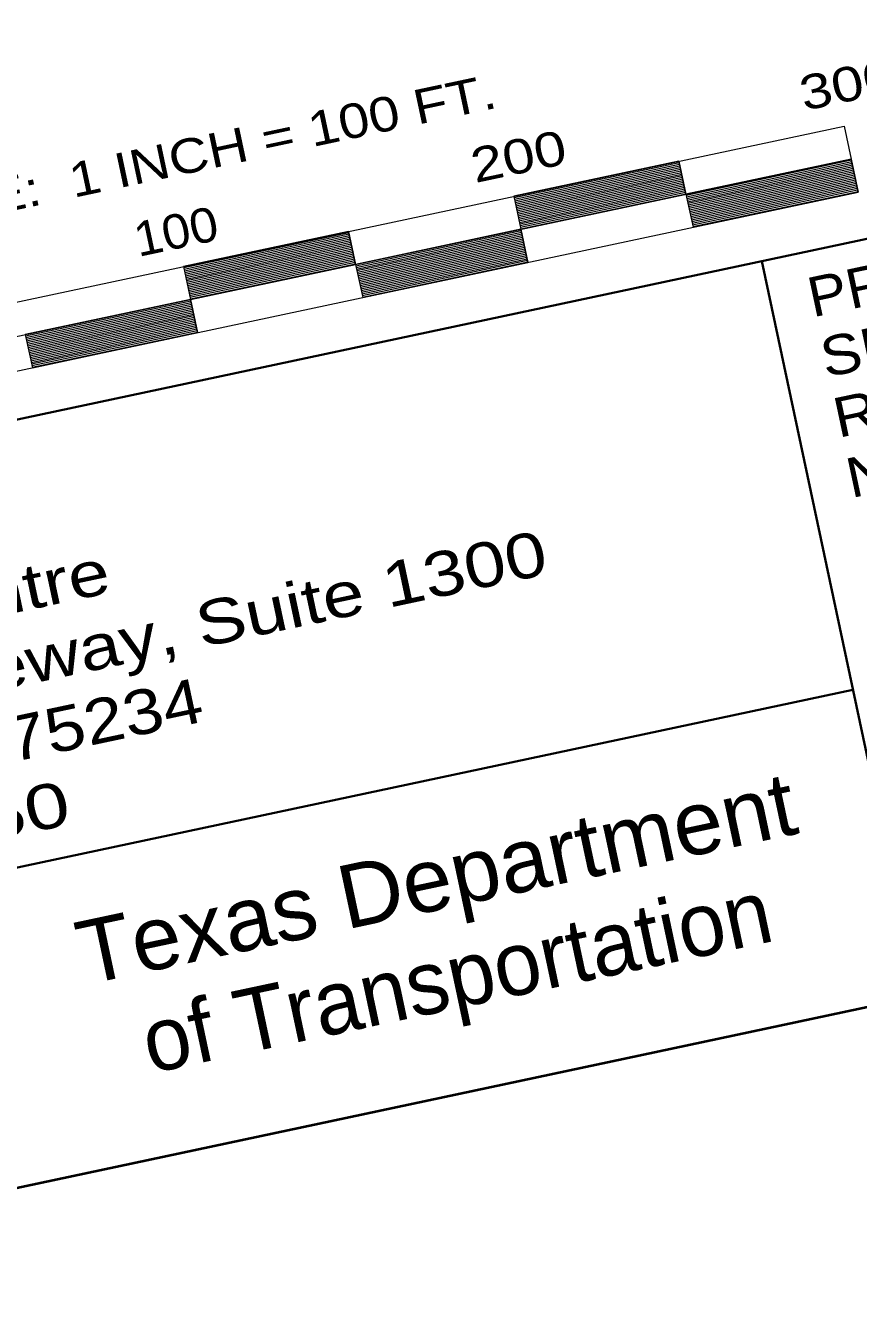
# Model space of a CAD drawing. Extents: x 2357218 to 2371708, y 6973728 to 6980157.
# Drawn here: x 2358239.3 to 2358486, y 6973919.3 to 6974296.3 of the extents above; entities that cross this region are included whole.
import ezdxf
from ezdxf.enums import TextEntityAlignment as Align

# ---------------------------------------------------------------- set-up
doc = ezdxf.new("R2010")
doc.units = 0
doc.header["$LTSCALE"] = 2
doc.layers.add('62', color=7, linetype='Continuous', lineweight=13)
doc.layers.add('63', color=7, linetype='Continuous', lineweight=13)

msp = doc.modelspace()

# ---------------------------------------------------------------- linework, layer by layer
at = {"layer": '62', "lineweight": 40}
msp.add_line((2371224.464, 6976712.679), (2358116.692, 6973926.537), dxfattribs=at)
at = {"layer": '62', "lineweight": 35}
for p, q in [((2358706.979, 6974279.557), (2358070.155, 6974144.195)), ((2358503.307, 6974010.333), (2358457.357, 6974226.499)), ((2358484.341, 6974099.558), (2358097.137, 6974017.255))]:
    msp.add_line(p, q, dxfattribs=at)
at = {"layer": '62'}
for p, q in [((2358090.44, 6974183.356), (2358481.753, 6974266.532)), ((2358481.753, 6974266.532), (2358483.832, 6974256.749)), ((2358092.52, 6974173.573), (2358483.832, 6974256.749)), ((2358384.006, 6974245.356), (2358432.918, 6974255.752)), ((2358384.11, 6974244.866), (2358433.024, 6974255.263)), ((2358432.837, 6974256.135), (2358434.916, 6974246.353)), ((2358434.973, 6974246.091), (2358483.887, 6974256.487)), ((2358435.077, 6974245.602), (2358483.99, 6974255.999)), ((2358435.18, 6974245.113), (2358484.095, 6974255.51)), ((2358435.284, 6974244.623), (2358484.199, 6974255.02)), ((2358483.832, 6974256.749), (2358485.911, 6974246.966)), ((2358384.214, 6974244.377), (2358433.127, 6974254.773)), ((2358384.317, 6974243.888), (2358433.231, 6974254.284)), ((2358384.421, 6974243.399), (2358433.335, 6974253.794)), ((2358384.525, 6974242.909), (2358433.438, 6974253.306)), ((2358384.63, 6974242.42), (2358433.543, 6974252.817)), ((2358384.733, 6974241.931), (2358433.646, 6974252.328)), ((2358384.837, 6974241.442), (2358433.75, 6974251.839)), ((2358384.942, 6974240.953), (2358433.854, 6974251.349)), ((2358435.388, 6974244.135), (2358484.302, 6974254.531)), ((2358435.492, 6974243.645), (2358484.406, 6974254.042)), ((2358435.596, 6974243.156), (2358484.51, 6974253.554)), ((2358435.7, 6974242.667), (2358484.615, 6974253.065)), ((2358435.805, 6974242.178), (2358484.718, 6974252.575)), ((2358435.909, 6974241.689), (2358484.822, 6974252.087)), ((2358436.013, 6974241.2), (2358484.927, 6974251.597)), ((2358385.045, 6974240.464), (2358433.959, 6974250.86)), ((2358385.15, 6974239.975), (2358434.063, 6974250.372)), ((2358385.253, 6974239.485), (2358434.166, 6974249.882)), ((2358385.358, 6974238.996), (2358434.27, 6974249.394)), ((2358385.461, 6974238.507), (2358434.374, 6974248.904)), ((2358385.565, 6974238.018), (2358434.479, 6974248.415)), ((2358385.669, 6974237.529), (2358434.583, 6974247.927)), ((2358385.772, 6974237.04), (2358434.686, 6974247.437)), ((2358436.117, 6974240.711), (2358485.031, 6974251.108)), ((2358436.219, 6974240.221), (2358485.135, 6974250.619)), ((2358436.324, 6974239.733), (2358485.238, 6974250.13)), ((2358436.428, 6974239.242), (2358485.342, 6974249.641)), ((2358436.532, 6974238.753), (2358485.446, 6974249.15)), ((2358436.636, 6974238.264), (2358485.55, 6974248.661)), ((2358436.74, 6974237.775), (2358485.655, 6974248.172)), ((2358436.845, 6974237.286), (2358485.758, 6974247.683)), ((2358383.925, 6974245.738), (2358386.004, 6974235.955)), ((2358385.877, 6974236.551), (2358434.791, 6974246.948)), ((2358385.981, 6974236.062), (2358434.894, 6974246.459)), ((2358434.916, 6974246.353), (2358436.996, 6974236.569)), ((2358436.948, 6974236.797), (2358485.863, 6974247.194)), ((2358286.157, 6974224.66), (2358335.07, 6974235.056)), ((2358286.261, 6974224.17), (2358335.174, 6974234.567)), ((2358286.365, 6974223.68), (2358335.279, 6974234.078)), ((2358286.468, 6974223.19), (2358335.382, 6974233.588)), ((2358286.572, 6974222.702), (2358335.487, 6974233.099)), ((2358286.676, 6974222.213), (2358335.59, 6974232.61)), ((2358335.01, 6974235.341), (2358337.089, 6974225.558)), ((2358337.17, 6974225.176), (2358386.083, 6974235.572)), ((2358337.275, 6974224.687), (2358386.188, 6974235.083)), ((2358337.378, 6974224.197), (2358386.292, 6974234.594)), ((2358337.482, 6974223.708), (2358386.397, 6974234.106)), ((2358337.587, 6974223.219), (2358386.5, 6974233.616)), ((2358337.69, 6974222.73), (2358386.604, 6974233.128)), ((2358337.794, 6974222.241), (2358386.709, 6974232.639)), ((2358386.004, 6974235.955), (2358388.082, 6974226.173)), ((2358286.78, 6974221.724), (2358335.694, 6974232.121)), ((2358286.885, 6974221.236), (2358335.797, 6974231.633)), ((2358286.988, 6974220.746), (2358335.902, 6974231.142)), ((2358287.093, 6974220.257), (2358336.006, 6974230.654)), ((2358287.197, 6974219.769), (2358336.109, 6974230.164)), ((2358287.3, 6974219.279), (2358336.214, 6974229.675)), ((2358287.404, 6974218.79), (2358336.318, 6974229.186)), ((2358287.508, 6974218.3), (2358336.421, 6974228.697)), ((2358337.898, 6974221.752), (2358386.812, 6974232.15)), ((2358338.002, 6974221.263), (2358386.917, 6974231.661)), ((2358338.106, 6974220.774), (2358387.02, 6974231.171)), ((2358338.209, 6974220.285), (2358387.124, 6974230.683)), ((2358338.314, 6974219.796), (2358387.229, 6974230.194)), ((2358338.418, 6974219.305), (2358387.332, 6974229.703)), ((2358338.523, 6974218.816), (2358387.437, 6974229.214)), ((2358338.625, 6974218.327), (2358387.54, 6974228.724)), ((2358286.096, 6974224.944), (2358288.175, 6974215.161)), ((2358287.613, 6974217.811), (2358336.526, 6974228.208)), ((2358287.716, 6974217.323), (2358336.629, 6974227.719)), ((2358287.82, 6974216.833), (2358336.733, 6974227.23)), ((2358287.925, 6974216.344), (2358336.837, 6974226.741)), ((2358288.028, 6974215.855), (2358336.941, 6974226.252)), ((2358288.133, 6974215.366), (2358337.046, 6974225.763)), ((2358337.089, 6974225.558), (2358339.168, 6974215.775)), ((2358338.729, 6974217.838), (2358387.644, 6974228.235)), ((2358338.833, 6974217.349), (2358387.748, 6974227.747)), ((2358338.937, 6974216.86), (2358387.852, 6974227.257)), ((2358339.042, 6974216.371), (2358387.957, 6974226.768)), ((2358339.146, 6974215.883), (2358388.06, 6974226.279)), ((2358239.342, 6974204.386), (2358288.255, 6974214.783)), ((2358239.446, 6974203.898), (2358288.359, 6974214.293)), ((2358239.549, 6974203.407), (2358288.464, 6974213.803)), ((2358288.175, 6974215.161), (2358290.254, 6974205.378)), ((2358239.653, 6974202.919), (2358288.567, 6974213.315)), ((2358239.757, 6974202.429), (2358288.672, 6974212.826)), ((2358239.861, 6974201.94), (2358288.776, 6974212.336)), ((2358239.965, 6974201.452), (2358288.879, 6974211.849)), ((2358240.07, 6974200.962), (2358288.983, 6974211.359)), ((2358240.174, 6974200.473), (2358289.087, 6974210.871)), ((2358240.277, 6974199.984), (2358289.192, 6974210.382)), ((2358240.382, 6974199.495), (2358289.296, 6974209.892)), ((2358240.484, 6974199.006), (2358289.4, 6974209.404)), ((2358240.589, 6974198.516), (2358289.503, 6974208.913)), ((2358240.693, 6974198.026), (2358289.607, 6974208.424)), ((2358240.797, 6974197.537), (2358289.712, 6974207.935)), ((2358240.901, 6974197.048), (2358289.815, 6974207.445)), ((2358241.005, 6974196.559), (2358289.919, 6974206.957)), ((2358241.11, 6974196.069), (2358290.023, 6974206.467)), ((2358241.213, 6974195.581), (2358290.127, 6974205.978)), ((2358239.262, 6974204.763), (2358241.34, 6974194.981)), ((2358241.317, 6974195.092), (2358290.232, 6974205.489))]:
    msp.add_line(p, q, dxfattribs=at)
for points in [[(2358386.004, 6974235.955), (2358434.916, 6974246.353), (2358432.837, 6974256.135), (2358383.925, 6974245.738)], [(2358436.996, 6974236.569), (2358485.911, 6974246.966), (2358483.832, 6974256.749), (2358434.916, 6974246.353)], [(2358288.175, 6974215.161), (2358337.089, 6974225.558), (2358335.01, 6974235.341), (2358286.096, 6974224.944)], [(2358339.168, 6974215.775), (2358388.082, 6974226.173), (2358386.004, 6974235.955), (2358337.089, 6974225.558)], [(2358241.34, 6974194.981), (2358290.254, 6974205.378), (2358288.175, 6974215.161), (2358239.262, 6974204.763)]]:
    msp.add_lwpolyline(points, close=True, dxfattribs=at)
at = {"layer": '63', "lineweight": 40}
msp.add_line((2371224.464, 6976712.679), (2358116.692, 6973926.537), dxfattribs=at)
at = {"layer": '63'}
for p, q in [((2358090.44, 6974183.356), (2358481.753, 6974266.532)), ((2358481.753, 6974266.532), (2358483.832, 6974256.749)), ((2358092.52, 6974173.573), (2358483.832, 6974256.749)), ((2358384.006, 6974245.356), (2358432.918, 6974255.752)), ((2358384.11, 6974244.866), (2358433.024, 6974255.263)), ((2358432.837, 6974256.135), (2358434.916, 6974246.353)), ((2358434.973, 6974246.091), (2358483.887, 6974256.487)), ((2358435.077, 6974245.602), (2358483.99, 6974255.999)), ((2358435.18, 6974245.113), (2358484.095, 6974255.51)), ((2358435.284, 6974244.623), (2358484.199, 6974255.02)), ((2358483.832, 6974256.749), (2358485.911, 6974246.966)), ((2358384.214, 6974244.377), (2358433.127, 6974254.773)), ((2358384.317, 6974243.888), (2358433.231, 6974254.284)), ((2358384.421, 6974243.399), (2358433.335, 6974253.794)), ((2358384.525, 6974242.909), (2358433.438, 6974253.306)), ((2358384.63, 6974242.42), (2358433.543, 6974252.817)), ((2358384.733, 6974241.931), (2358433.646, 6974252.328)), ((2358384.837, 6974241.442), (2358433.75, 6974251.839)), ((2358384.942, 6974240.953), (2358433.854, 6974251.349)), ((2358435.388, 6974244.135), (2358484.302, 6974254.531)), ((2358435.492, 6974243.645), (2358484.406, 6974254.042)), ((2358435.596, 6974243.156), (2358484.51, 6974253.554)), ((2358435.7, 6974242.667), (2358484.615, 6974253.065)), ((2358435.805, 6974242.178), (2358484.718, 6974252.575)), ((2358435.909, 6974241.689), (2358484.822, 6974252.087)), ((2358436.013, 6974241.2), (2358484.927, 6974251.597)), ((2358385.045, 6974240.464), (2358433.959, 6974250.86)), ((2358385.15, 6974239.975), (2358434.063, 6974250.372)), ((2358385.253, 6974239.485), (2358434.166, 6974249.882)), ((2358385.358, 6974238.996), (2358434.27, 6974249.394)), ((2358385.461, 6974238.507), (2358434.374, 6974248.904)), ((2358385.565, 6974238.018), (2358434.479, 6974248.415)), ((2358385.669, 6974237.529), (2358434.583, 6974247.927)), ((2358385.772, 6974237.04), (2358434.686, 6974247.437)), ((2358436.117, 6974240.711), (2358485.031, 6974251.108)), ((2358436.219, 6974240.221), (2358485.135, 6974250.619)), ((2358436.324, 6974239.733), (2358485.238, 6974250.13)), ((2358436.428, 6974239.242), (2358485.342, 6974249.641)), ((2358436.532, 6974238.753), (2358485.446, 6974249.15)), ((2358436.636, 6974238.264), (2358485.55, 6974248.661)), ((2358436.74, 6974237.775), (2358485.655, 6974248.172)), ((2358436.845, 6974237.286), (2358485.758, 6974247.683)), ((2358094.598, 6974163.791), (2358485.911, 6974246.966)), ((2358383.925, 6974245.738), (2358386.004, 6974235.955)), ((2358385.877, 6974236.551), (2358434.791, 6974246.948)), ((2358385.981, 6974236.062), (2358434.894, 6974246.459)), ((2358434.916, 6974246.353), (2358436.996, 6974236.569)), ((2358436.948, 6974236.797), (2358485.863, 6974247.194)), ((2358286.157, 6974224.66), (2358335.07, 6974235.056)), ((2358286.261, 6974224.17), (2358335.174, 6974234.567)), ((2358286.365, 6974223.68), (2358335.279, 6974234.078)), ((2358286.468, 6974223.19), (2358335.382, 6974233.588)), ((2358286.572, 6974222.702), (2358335.487, 6974233.099)), ((2358286.676, 6974222.213), (2358335.59, 6974232.61)), ((2358335.01, 6974235.341), (2358337.089, 6974225.558)), ((2358337.17, 6974225.176), (2358386.083, 6974235.572)), ((2358337.275, 6974224.687), (2358386.188, 6974235.083)), ((2358337.378, 6974224.197), (2358386.292, 6974234.594)), ((2358337.482, 6974223.708), (2358386.397, 6974234.106)), ((2358337.587, 6974223.219), (2358386.5, 6974233.616)), ((2358337.69, 6974222.73), (2358386.604, 6974233.128)), ((2358337.794, 6974222.241), (2358386.709, 6974232.639)), ((2358386.004, 6974235.955), (2358388.082, 6974226.173)), ((2358286.78, 6974221.724), (2358335.694, 6974232.121)), ((2358286.885, 6974221.236), (2358335.797, 6974231.633)), ((2358286.988, 6974220.746), (2358335.902, 6974231.142)), ((2358287.093, 6974220.257), (2358336.006, 6974230.654)), ((2358287.197, 6974219.769), (2358336.109, 6974230.164)), ((2358287.3, 6974219.279), (2358336.214, 6974229.675)), ((2358287.404, 6974218.79), (2358336.318, 6974229.186)), ((2358287.508, 6974218.3), (2358336.421, 6974228.697)), ((2358337.898, 6974221.752), (2358386.812, 6974232.15)), ((2358338.002, 6974221.263), (2358386.917, 6974231.661)), ((2358338.106, 6974220.774), (2358387.02, 6974231.171)), ((2358338.209, 6974220.285), (2358387.124, 6974230.683)), ((2358338.314, 6974219.796), (2358387.229, 6974230.194)), ((2358338.418, 6974219.305), (2358387.332, 6974229.703)), ((2358338.523, 6974218.816), (2358387.437, 6974229.214)), ((2358338.625, 6974218.327), (2358387.54, 6974228.724)), ((2358286.096, 6974224.944), (2358288.175, 6974215.161)), ((2358287.613, 6974217.811), (2358336.526, 6974228.208)), ((2358287.716, 6974217.323), (2358336.629, 6974227.719)), ((2358287.82, 6974216.833), (2358336.733, 6974227.23)), ((2358287.925, 6974216.344), (2358336.837, 6974226.741)), ((2358288.028, 6974215.855), (2358336.941, 6974226.252)), ((2358288.133, 6974215.366), (2358337.046, 6974225.763)), ((2358337.089, 6974225.558), (2358339.168, 6974215.775)), ((2358338.729, 6974217.838), (2358387.644, 6974228.235)), ((2358338.833, 6974217.349), (2358387.748, 6974227.747)), ((2358338.937, 6974216.86), (2358387.852, 6974227.257)), ((2358339.042, 6974216.371), (2358387.957, 6974226.768)), ((2358339.146, 6974215.883), (2358388.06, 6974226.279)), ((2358239.342, 6974204.386), (2358288.255, 6974214.783)), ((2358239.446, 6974203.898), (2358288.359, 6974214.293)), ((2358239.549, 6974203.407), (2358288.464, 6974213.803)), ((2358288.175, 6974215.161), (2358290.254, 6974205.378)), ((2358239.653, 6974202.919), (2358288.567, 6974213.315)), ((2358239.757, 6974202.429), (2358288.672, 6974212.826)), ((2358239.861, 6974201.94), (2358288.776, 6974212.336)), ((2358239.965, 6974201.452), (2358288.879, 6974211.849)), ((2358240.07, 6974200.962), (2358288.983, 6974211.359)), ((2358240.174, 6974200.473), (2358289.087, 6974210.871)), ((2358240.277, 6974199.984), (2358289.192, 6974210.382)), ((2358240.382, 6974199.495), (2358289.296, 6974209.892)), ((2358240.484, 6974199.006), (2358289.4, 6974209.404)), ((2358240.589, 6974198.516), (2358289.503, 6974208.913)), ((2358240.693, 6974198.026), (2358289.607, 6974208.424)), ((2358240.797, 6974197.537), (2358289.712, 6974207.935)), ((2358240.901, 6974197.048), (2358289.815, 6974207.445)), ((2358241.005, 6974196.559), (2358289.919, 6974206.957)), ((2358241.11, 6974196.069), (2358290.023, 6974206.467)), ((2358241.213, 6974195.581), (2358290.127, 6974205.978)), ((2358239.262, 6974204.763), (2358241.34, 6974194.981)), ((2358241.317, 6974195.092), (2358290.232, 6974205.489))]:
    msp.add_line(p, q, dxfattribs=at)
for points in [[(2358386.004, 6974235.955), (2358434.916, 6974246.353), (2358432.837, 6974256.135), (2358383.925, 6974245.738)], [(2358436.996, 6974236.569), (2358485.911, 6974246.966), (2358483.832, 6974256.749), (2358434.916, 6974246.353)], [(2358288.175, 6974215.161), (2358337.089, 6974225.558), (2358335.01, 6974235.341), (2358286.096, 6974224.944)], [(2358339.168, 6974215.775), (2358388.082, 6974226.173), (2358386.004, 6974235.955), (2358337.089, 6974225.558)], [(2358241.34, 6974194.981), (2358290.254, 6974205.378), (2358288.175, 6974215.161), (2358239.262, 6974204.763)]]:
    msp.add_lwpolyline(points, close=True, dxfattribs=at)

# ---------------------------------------------------------------- texts
at = {"layer": '62'}
for s, height, width, p in [('FRONTAGE ROAD DESIGN SPEED VARIABLE 35 TO 40 MPH', 10.2, 1.2, (2358378.055, 6974329.019)), ('300', 10.2, 1.25, (2358483.754, 6974273.951)), ('SCALE:  1 INCH = 100 FT.', 10.2, 1.2, (2358283.549, 6974251.641)), ('200', 10.2, 1.25, (2358386.378, 6974252.589)), ('100', 10.2, 1.1, (2358284.944, 6974230.352)), ('Texas Department', 18.76, 1.05, (2358362.855, 6974034.644))]:
    msp.add_text(s, height=height, rotation=12, dxfattribs=dict(at, width=width)).set_placement(p, align=Align.CENTER)
for s, height, width, p in [('PRELIMINARY PLAN', 11.74, 1.1, (2358472.418, 6974209.845)), ('SUBMITTAL FOR', 11.74, 1.15, (2358476.212, 6974192.001)), ('NOT FOR CONSTRUCTION.', 11.74, 1.15, (2358483.798, 6974156.313)), ('REVIEW ONLY', 11.74, 1.15, (2358480.005, 6974174.157)), ('3010 LBJ Freeway, Suite 1300', 13.22, 1.25, (2358099.138, 6974071.19)), ('Graystone Centre', 13.22, 1.25, (2358094.657, 6974092.268)), ('Dallas, Texas 75234', 13.22, 1.2, (2358103.618, 6974050.113)), ('972-406-6950', 13.22, 1.35, (2358108.098, 6974029.035)), ('TURN LEVEL 62 ON AND LEVEL 63 OFF TO PLOT COLOR', 25, 1.3, (2358405.231, 6973761.729)), ('PLOTTING INSTRUCTIONS FOR BORDER FILE:', 25, 1.25, (2358397.538, 6973797.922)), ('TURN LEVEL 63 ON AND LEVEL 62 OFF TO PLOT B/W', 25, 1.3, (2358412.922, 6973725.536))]:
    msp.add_text(s, height=height, rotation=12, dxfattribs=dict(at, width=width)).set_placement(p)
msp.add_text('of Transportation', height=18.76, rotation=12, dxfattribs=at).set_placement((2358368.952, 6974005.624), align=Align.CENTER)
at = {"layer": '63'}
for s, height, width, p in [('300', 10.2, 1.25, (2358483.754, 6974273.951)), ('200', 10.2, 1.25, (2358386.378, 6974252.589)), ('100', 10.2, 1.1, (2358284.944, 6974230.352)), ('Texas Department', 18.76, 1.05, (2358362.855, 6974034.644))]:
    msp.add_text(s, height=height, rotation=12, dxfattribs=dict(at, width=width)).set_placement(p, align=Align.CENTER)
msp.add_text('of Transportation', height=18.76, rotation=12, dxfattribs=at).set_placement((2358368.952, 6974005.624), align=Align.CENTER)

doc.saveas('drawing.dxf')
